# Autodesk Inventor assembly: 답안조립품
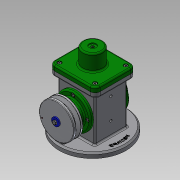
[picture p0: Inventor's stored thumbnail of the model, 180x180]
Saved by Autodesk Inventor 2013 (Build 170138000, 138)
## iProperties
Created: 2019-08
Part Number: 답안조립품
Document SubType Name: Assembly
Designer: Administrator
Author: Administrator
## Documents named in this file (17)
- C:\Documents and Settings\Administrator\바탕 화면\490804V1014\답안조립품.iam
- C:\Documents and Settings\Administrator\바탕 화면\490804V1014\본체.ipt
- C:\Documents and Settings\Administrator\바탕 화면\490804V1014\편심축.ipt
- C:\Documents and Settings\Administrator\바탕 화면\490804V1014\베어링 17 x 40 x 12.ipt
- C:\Documents and Settings\Administrator\바탕 화면\490804V1014\앞커버.ipt
- C:\Documents and Settings\Administrator\바탕 화면\490804V1014\링크.ipt
- C:\Documents and Settings\Administrator\바탕 화면\490804V1014\클레비스 핀 6 x 22.ipt
- 클레비스 핀 6 x 22.ipt
- C:\Documents and Settings\Administrator\바탕 화면\490804V1014\슬라이더.ipt
- C:\Documents and Settings\Administrator\바탕 화면\490804V1014\덮개.ipt
- C:\Documents and Settings\Administrator\바탕 화면\490804V1014\볼트 M4 x 8.ipt
- C:\Documents and Settings\Administrator\바탕 화면\490804V1014\오일 실 17 30 8.ipt
- C:\Documents and Settings\Administrator\바탕 화면\490804V1014\키 4 x 4 x 12.ipt
- C:\Documents and Settings\Administrator\바탕 화면\490804V1014\E-링.ipt
- C:\Documents and Settings\Administrator\바탕 화면\490804V1014\V-벨트풀리.ipt
- C:\Documents and Settings\Administrator\바탕 화면\490804V1014\와셔 4x16.ipt
- C:\Documents and Settings\Administrator\바탕 화면\490804V1014\볼트 M4 x 10.ipt
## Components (2 placed, 2 different names)
1. E-링:1
2. V-벨트풀리:1
